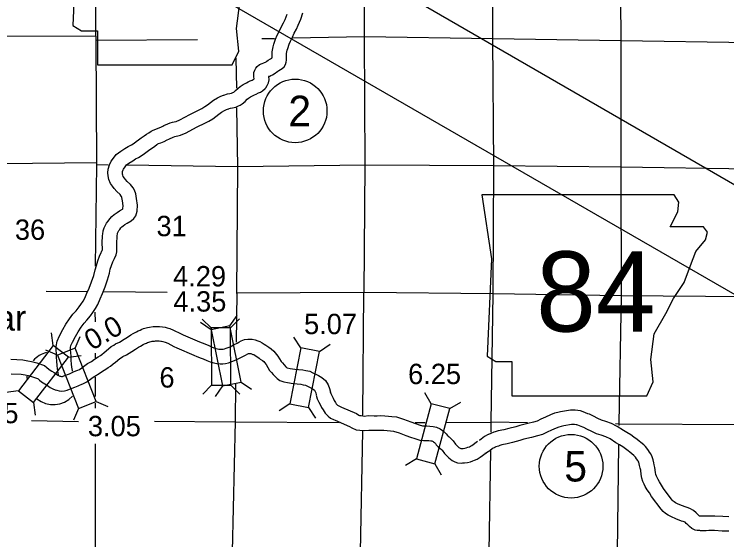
# Model space of a CAD drawing. Extents: x 369523 to 838377, y 495025 to 936819.
# Drawn here: x 509009 to 538589, y 844599 to 866414 of the extents above; entities that cross this region are included whole.
import ezdxf

# ---------------------------------------------------------------- set-up
doc = ezdxf.new("R2010")
doc.units = 0
for name, color, linetype in [('1', 7, 'Continuous'), ('21', 7, 'Continuous'), ('22', 7, 'Continuous'), ('DSN_BRDG_Annotation', 7, 'Continuous'), ('DSN_DRFT_Common-Line', 7, 'Continuous'), ('DSN_DRFT_Junk-No-Plot', 7, 'Continuous'), ('Level 1', 7, 'Continuous'), ('Level 15', 7, 'Continuous'), ('Level 21', 7, 'Continuous'), ('Level 22', 7, 'Continuous')]:
    doc.layers.add(name, color=color, linetype=linetype)

msp = doc.modelspace()

# ---------------------------------------------------------------- linework, layer by layer
at = {"layer": '1'}
for start, end in [(104.6734, 138.959), (176.1329, 180.9903), (231.4918, 316.9545)]:
    msp.add_arc((510629, 851310), 1100, start, end, dxfattribs=at)
at = {"layer": '21'}
for p, q in [((459282, 905322), (715348, 757482)), ((708796, 756692), (471020, 893972))]:
    msp.add_line(p, q, dxfattribs=at)
at = {"layer": '22'}
for points in [[(511222, 872658), (511622, 869994), (511444, 865952), (511799, 865730), (512465, 865730), (512465, 864309), (518061, 864309), (518327, 864887), (518239, 865819), (518372, 866885), (518860, 867729), (519171, 868350), (519615, 869017), (519882, 869727), (520104, 870304), (520503, 870793), (520592, 871104), (520415, 871326), (519038, 871326), (519349, 871948), (519393, 872347), (519209, 872654)], [(528426, 858920), (528825, 856256), (528648, 852215), (529003, 851993), (529669, 851993), (529669, 850571), (535265, 850571), (535531, 851149), (535442, 852081), (535576, 853147), (536064, 853991), (536375, 854613), (536819, 855279), (537086, 855989), (537308, 856567), (537707, 857055), (537796, 857366), (537618, 857588), (536242, 857588), (536553, 858210), (536597, 858610), (536413, 858917)]]:
    msp.add_lwpolyline(points, close=True, dxfattribs=at)
at = {"layer": 'DSN_DRFT_Common-Line'}
for centre in [(520673, 862400), (532128, 847652)]:
    msp.add_circle(centre, 1320, dxfattribs=at)
at = {"layer": 'Level 1'}
for points in [[(517713, 863059), (517859, 863105), (517963, 863119), (518023, 863133), (518061, 863149), (518086, 863163), (518126, 863186), (518201, 863247), (518287, 863332), (518390, 863413), (518512, 863493), (518645, 863566), (518723, 863608), (518800, 863643), (518889, 863684), (518933, 863707), (518952, 863719), (518974, 863739), (518952, 863820), (518952, 863908), (518960, 863991), (518992, 864097), (519042, 864175), (519091, 864239), (519194, 864324), (519298, 864367), (519365, 864390), (519398, 864405), (519442, 864428), (519463, 864440), (519493, 864463), (519553, 864510), (519646, 864567), (519691, 864592), (519714, 864607), (519715, 864616), (519713, 864689), (519712, 864850), (519758, 865061), (519790, 865175), (519862, 865382), (519928, 865545), (520017, 865729), (520103, 865907), (520190, 866064), (520250, 866195), (520341, 866414)], [(517896, 862487), (517992, 862518), (518072, 862529), (518207, 862560), (518317, 862605), (518382, 862640), (518470, 862693), (518601, 862798), (518685, 862882), (518741, 862926), (518822, 862979), (518932, 863039), (518989, 863070), (519048, 863096), (519153, 863145), (519232, 863186), (519316, 863239), (519420, 863333), (519449, 863363), (519512, 863461), (519561, 863571), (519586, 863696), (519572, 863823), (519571, 863827), (519586, 863832), (519661, 863866), (519732, 863903), (519795, 863939), (519856, 863985), (519895, 864015), (519953, 864051), (520000, 864078), (520060, 864116), (520133, 864160), (520213, 864229), (520272, 864324), (520298, 864428), (520306, 864506), (520316, 864589), (520313, 864699), (520312, 864787), (520340, 864916), (520363, 864994), (520424, 865172), (520476, 865302), (520557, 865467), (520636, 865630), (520726, 865794), (520800, 865955), (520906, 866210), (520989, 866479)], [(510845, 851427), (510832, 851533), (510803, 851694), (510794, 851834), (510772, 852015), (510769, 852175), (510757, 852331), (510747, 852464), (510749, 852628), (510785, 852837), (510887, 853059), (511022, 853321), (511153, 853545), (511301, 853766), (511444, 853964), (511574, 854108), (511708, 854263), (511780, 854363), (511868, 854502), (511939, 854628), (512027, 854831), (512117, 855046), (512218, 855304), (512309, 855568), (512375, 855809), (512417, 855990), (512474, 856174), (512550, 856370), (512620, 856524), (512635, 856552), (512664, 856616), (512667, 856631), (512669, 856679), (512662, 856917), (512679, 857231), (512684, 857287), (512706, 857421), (512738, 857543), (512840, 857738), (512902, 857829), (512977, 857928), (513058, 858016), (513161, 858106), (513275, 858185), (513381, 858248), (513509, 858329), (513517, 858335), (513523, 858353), (513529, 858464), (513497, 858669), (513475, 858807), (513458, 858855), (513453, 858864), (513400, 858929), (513262, 859056), (513161, 859176), (513086, 859275), (513011, 859394), (512933, 859555), (512909, 859700), (512900, 859834), (512913, 859982), (512958, 860164), (513033, 860317), (513132, 860437), (513239, 860593), (513434, 860733), (513604, 860837), (513744, 860930), (513873, 860997), (513989, 861064), (514070, 861126), (514169, 861194), (514278, 861280), (514397, 861365), (514501, 861437), (514590, 861498), (514690, 861567), (514777, 861604), (514886, 861640), (514988, 861679), (515092, 861733), (515174, 861774), (515224, 861795), (515382, 861862), (515489, 861904), (515584, 861930), (515649, 861946), (515728, 861968), (515887, 862030), (516295, 862259), (516683, 862445), (516797, 862505), (516919, 862578), (517027, 862659), (517153, 862749), (517285, 862846), (517452, 862948), (517579, 863008), (517698, 863053)], [(511429, 851594), (511425, 851622), (511400, 851766), (511392, 851889), (511371, 852056), (511369, 852204), (511355, 852376), (511347, 852483), (511348, 852574), (511363, 852658), (511426, 852797), (511548, 853032), (511661, 853226), (511794, 853423), (511912, 853587), (512024, 853712), (512179, 853891), (512277, 854027), (512383, 854194), (512477, 854361), (512579, 854596), (512673, 854821), (512781, 855097), (512882, 855390), (512957, 855662), (512997, 855833), (513041, 855977), (513103, 856138), (513155, 856253), (513171, 856281), (513237, 856426), (513265, 856555), (513270, 856676), (513262, 856910), (513278, 857187), (513280, 857212), (513294, 857298), (513301, 857324), (513356, 857430), (513389, 857479), (513437, 857541), (513478, 857586), (513530, 857632), (513599, 857679), (513695, 857737), (513862, 857842), (513971, 857933), (514053, 858049), (514117, 858236), (514132, 858493), (514090, 858764), (514059, 858953), (514006, 859108), (513946, 859208), (513839, 859341), (513696, 859472), (513629, 859552), (513580, 859616), (513537, 859685), (513511, 859739), (513506, 859769), (513502, 859827), (513507, 859883), (513525, 859958), (513540, 859989), (513612, 860075), (513675, 860168), (513766, 860233), (513926, 860331), (514048, 860412), (514162, 860471), (514324, 860565), (514421, 860640), (514525, 860710), (514638, 860800), (514742, 860874), (514841, 860942), (514930, 861003), (514981, 861039), (514990, 861042), (515088, 861075), (515233, 861130), (515363, 861197), (515428, 861229), (515461, 861244), (515610, 861307), (515678, 861334), (515735, 861349), (515801, 861366), (515917, 861397), (516144, 861486), (516571, 861726), (516954, 861909), (517091, 861982), (517255, 862079), (517382, 862175), (517505, 862263), (517620, 862347), (517739, 862419), (517815, 862456), (517911, 862492)], [(511071, 851400), (511300, 851493), (511408, 851537), (511469, 851568), (511567, 851607), (511647, 851636), (511717, 851670), (511809, 851735), (511933, 851839), (512054, 851910), (512210, 852004), (512338, 852097), (512492, 852194), (512589, 852252), (512650, 852292), (512748, 852375), (512831, 852435), (513036, 852616), (513142, 852680), (513219, 852729), (513380, 852807), (513568, 852919), (513714, 853013), (513851, 853100), (513953, 853159), (514084, 853230), (514154, 853266), (514231, 853303), (514301, 853338), (514373, 853365), (514482, 853393), (514537, 853407), (514621, 853430), (514771, 853445), (514843, 853452), (514946, 853453), (515043, 853451), (515170, 853444), (515275, 853422), (515355, 853399), (515468, 853364), (515627, 853304), (515910, 853164), (516020, 853108), (516694, 852813), (516804, 852771), (516984, 852699), (517086, 852661), (517229, 852597), (517340, 852557), (517452, 852520), (517502, 852509), (517567, 852505), (517628, 852505), (517683, 852512), (517742, 852524), (517807, 852549), (517892, 852579), (517968, 852612), (518046, 852652), (518113, 852689), (518267, 852765), (518337, 852797), (518434, 852850), (518575, 852917), (518707, 852930), (518804, 852931), (518884, 852931), (519013, 852898), (519117, 852861), (519201, 852832), (519305, 852771), (519384, 852722), (519456, 852672), (519532, 852620), (519573, 852587), (519679, 852518), (519786, 852422), (519848, 852355), (519955, 852225), (520090, 851997), (520141, 851943), (520214, 851857), (520289, 851773), (520310, 851753), (520346, 851742), (520471, 851715), (520663, 851680), (520808, 851671), (520994, 851646), (521117, 851625), (521285, 851592), (521410, 851533), (521532, 851476), (521647, 851414), (521774, 851338), (521930, 851205), (522036, 851037), (522102, 850879), (522132, 850728)], [(511298, 850844), (511527, 850938), (511658, 850991), (511716, 851021), (511781, 851047), (511880, 851083), (512021, 851151), (512175, 851259), (512281, 851348), (512360, 851394), (512541, 851503), (512675, 851600), (512808, 851684), (512906, 851743), (513007, 851808), (513119, 851903), (513207, 851967), (513391, 852129), (513460, 852170), (513514, 852205), (513664, 852278), (513885, 852409), (514037, 852508), (514162, 852587), (514247, 852636), (514363, 852699), (514420, 852728), (514494, 852764), (514539, 852786), (514554, 852792), (514633, 852812), (514689, 852827), (514729, 852837), (514834, 852848), (514878, 852853), (514942, 852853), (515021, 852852), (515089, 852848), (515128, 852840), (515184, 852824), (515274, 852796), (515388, 852753), (515640, 852628), (515763, 852566), (516467, 852257), (516586, 852212), (516769, 852139), (516859, 852106), (517004, 852040), (517144, 851989), (517293, 851940), (517422, 851912), (517552, 851905), (517667, 851906), (517779, 851920), (517908, 851945), (518014, 851985), (518112, 852020), (518223, 852069), (518328, 852122), (518392, 852157), (518525, 852223), (518606, 852260), (518707, 852316), (518737, 852330), (518737, 852330), (518808, 852331), (518811, 852331), (518837, 852324), (518918, 852295), (518950, 852284), (518994, 852258), (519055, 852220), (519115, 852179), (519172, 852140), (519219, 852101), (519313, 852040), (519366, 851993), (519396, 851960), (519462, 851879), (519609, 851632), (519694, 851543), (519762, 851463), (519855, 851359), (519920, 851294), (520036, 851209), (520195, 851161), (520353, 851126), (520592, 851083), (520750, 851074), (520904, 851053), (521008, 851035), (521096, 851018), (521155, 850990), (521261, 850940), (521350, 850892), (521423, 850849), (521472, 850807), (521502, 850760), (521525, 850703), (521544, 850609)], [(508870, 852095), (509368, 852067), (509571, 852033), (509732, 851998), (509949, 851937), (510260, 851831), (510368, 851747), (510450, 851684), (510500, 851637), (510568, 851596), (510665, 851547), (510762, 851472), (510817, 851429), (510850, 851413), (510897, 851395), (510927, 851386), (510970, 851376), (510982, 851375), (511016, 851376), (511066, 851398)], [(508886, 851493), (509301, 851470), (509457, 851443), (509587, 851416), (509770, 851363), (509970, 851296), (509999, 851273), (510062, 851225), (510136, 851156), (510276, 851071), (510343, 851037), (510394, 850997), (510503, 850913), (510613, 850862), (510707, 850825), (510777, 850806), (510877, 850781), (510970, 850774), (511094, 850778), (511203, 850803), (511303, 850846)], [(522130, 850739), (522147, 850666), (522191, 850584), (522247, 850474), (522291, 850382), (522342, 850302), (522380, 850237), (522390, 850222), (522403, 850208), (522423, 850190), (522450, 850168), (522507, 850146), (522595, 850100), (523215, 849837), (523314, 849770), (523347, 849756), (523412, 849751), (523554, 849735), (523699, 849755), (523951, 849750), (524074, 849750), (524199, 849753), (524394, 849750), (524551, 849730), (524689, 849719), (524879, 849696), (525174, 849605), (525476, 849495), (525662, 849428), (525823, 849372), (525963, 849330), (526029, 849324), (526076, 849323), (526140, 849323), (526258, 849317), (526407, 849305), (526544, 849269), (526689, 849205), (526785, 849139), (526853, 849079), (526938, 849003), (526992, 848928), (527021, 848898), (527061, 848866), (527151, 848788), (527236, 848707), (527333, 848563), (527400, 848498), (527442, 848453), (527473, 848431), (527517, 848397), (527543, 848384), (527550, 848384), (527586, 848385), (527645, 848389), (527715, 848400), (527770, 848413), (527840, 848438), (527907, 848462), (527953, 848480), (528012, 848518), (528244, 848690)], [(521547, 850598), (521582, 850452), (521659, 850307), (521708, 850209), (521765, 850090), (521831, 849987), (521869, 849924), (521911, 849856), (521983, 849778), (522035, 849732), (522144, 849643), (522259, 849598), (522339, 849557), (522927, 849307), (523028, 849240), (523202, 849167), (523354, 849154), (523562, 849131), (523733, 849154), (523947, 849150), (524083, 849151), (524201, 849153), (524350, 849151), (524488, 849133), (524629, 849121), (524754, 849106), (524983, 849036), (525272, 848930), (525462, 848863), (525637, 848801), (525849, 848737), (525994, 848725), (526070, 848723), (526126, 848723), (526219, 848718), (526305, 848711), (526344, 848701), (526396, 848678), (526416, 848665), (526455, 848630), (526491, 848598), (526529, 848545), (526613, 848456), (526677, 848405), (526747, 848344), (526775, 848318), (526871, 848175), (526973, 848077), (527046, 847998), (527116, 847949), (527196, 847888), (527296, 847837), (527415, 847786), (527558, 847783), (527618, 847786), (527707, 847792), (527831, 847810), (527945, 847838), (528042, 847873), (528114, 847899), (528227, 847942), (528354, 848025), (528602, 848208)], [(538669, 845555), (538421, 845562), (538094, 845577), (537937, 845580), (537829, 845581), (537716, 845574), (537612, 845573), (537554, 845574), (537461, 845581), (537437, 845601), (537397, 845639), (537320, 845718), (537203, 845819), (537063, 845897), (536952, 845933), (536906, 845947), (536714, 846021), (536551, 846094), (536466, 846136), (536403, 846178), (536367, 846207), (536330, 846249), (535964, 846729), (535884, 846868), (535793, 846998), (535736, 847094), (535710, 847152), (535673, 847237), (535650, 847306), (535636, 847397), (535606, 847601), (535577, 847711), (535560, 847795), (535538, 847913), (535491, 848047), (535439, 848161), (535386, 848235), (535337, 848308), (535272, 848398), (535213, 848465), (535149, 848537), (535028, 848631), (534952, 848695), (534873, 848764), (534737, 848860), (534608, 848951), (534443, 849058), (534299, 849134), (534045, 849305), (533802, 849420), (533572, 849508), (533391, 849561), (533244, 849630), (533053, 849725), (532888, 849808), (532821, 849832), (532625, 849911), (532514, 849951), (532405, 849970), (532298, 849977), (532109, 849982), (531693, 849913), (531579, 849881), (531432, 849852), (531269, 849781), (531068, 849691), (530874, 849605), (530717, 849528), (530569, 849485), (530337, 849421), (530004, 849348), (529826, 849289), (529537, 849214), (529341, 849161), (529102, 849118), (528980, 849078), (528926, 849059), (528791, 849014), (528704, 848975)], [(538669, 844954), (538398, 844962), (538075, 844977), (537928, 844980), (537844, 844981), (537738, 844974), (537611, 844973), (537493, 844975), (537473, 844978), (537361, 844987), (537276, 845004), (537138, 845071), (537038, 845151), (536973, 845215), (536909, 845280), (536857, 845325), (536821, 845345), (536776, 845359), (536714, 845377), (536482, 845467), (536296, 845551), (536164, 845615), (536047, 845695), (535954, 845769), (535867, 845866), (535462, 846396), (535376, 846547), (535289, 846672), (535204, 846815), (535161, 846909), (535112, 847023), (535066, 847162), (535043, 847306), (535017, 847481), (534992, 847576), (534972, 847679), (534957, 847757), (534934, 847823), (534917, 847860), (534893, 847893), (534845, 847964), (534801, 848025), (534763, 848069), (534738, 848096), (534651, 848164), (534562, 848239), (534501, 848292), (534392, 848370), (534272, 848453), (534139, 848540), (533991, 848618), (533748, 848782), (533566, 848868), (533380, 848939), (533177, 848999), (532983, 849090), (532785, 849188), (532654, 849255), (532609, 849270), (532409, 849351), (532359, 849369), (532336, 849373), (532271, 849377), (532149, 849381), (531824, 849327), (531719, 849297), (531612, 849276), (531512, 849232), (531312, 849143), (531128, 849061), (530935, 848967), (530733, 848907), (530480, 848838), (530163, 848769), (529996, 848713), (529691, 848634), (529473, 848576), (529250, 848535), (529172, 848509), (529119, 848491), (529008, 848454), (528948, 848427)], [(528689, 848968), (528536, 848889), (528399, 848781), (528333, 848737), (528307, 848726)], [(528963, 848434), (528862, 848382), (528753, 848296), (528620, 848206), (528539, 848173)]]:
    msp.add_lwpolyline(points, dxfattribs=at)
at = {"layer": 'Level 15'}
for points in [[(512401, 865502), (512381, 870748), (512380, 870824), (512358, 876028)], [(512401, 865502), (512400, 865320), (512419, 860240), (512421, 860162), (512372, 855951)], [(512056, 854894), (510337, 854909)], [(515352, 854864), (512732, 854888)], [(528893, 854803), (523543, 854865), (523503, 854861), (518255, 854837), (518221, 854838)], [(549623, 854534), (544781, 854632), (539490, 854682), (539446, 854681), (534205, 854724), (528893, 854803)], [(512361, 854052), (512362, 853649)], [(512364, 852338), (512364, 852150)], [(512365, 851355), (512367, 850544)], [(512367, 850276), (512368, 850061)], [(512368, 848578), (512365, 844229), (512361, 844207), (512365, 838913), (512342, 833591)]]:
    msp.add_lwpolyline(points, dxfattribs=at)
at = {"layer": 'Level 21'}
for p, q in [((517191, 853391), (516815, 853762)), ((517964, 853473), (518258, 853912)), ((517982, 853396), (518354, 853771)), ((517187, 853319), (516748, 853613)), ((510630, 852666), (510562, 853189)), ((511535, 852550), (511743, 853035)), ((520905, 852572), (520611, 853011)), ((521682, 852419), (522121, 852713)), ((510799, 852257), (510314, 852466)), ((511257, 852182), (511781, 852250)), ((518426, 851143), (518865, 850849)), ((509180, 850784), (508656, 850716)), ((517205, 851015), (516834, 850639)), ((517650, 850989), (517356, 850550)), ((517997, 851020), (518373, 850648)), ((526322, 850247), (526057, 850704)), ((509807, 850300), (509875, 849777)), ((512414, 850343), (512899, 850134)), ((520445, 850241), (520006, 849947)), ((527087, 850043), (527544, 850307)), ((511678, 850050), (511470, 849565)), ((521222, 850088), (521516, 849649)), ((525709, 847952), (525252, 847687)), ((526474, 847747), (526738, 847290))]:
    msp.add_line(p, q, dxfattribs=at)
for points in [[(517187, 853319), (517650, 850989), (518426, 851143), (517964, 853473)], [(517997, 851020), (517982, 853396), (517191, 853391), (517205, 851015)], [(509807, 850300), (511257, 852182), (510630, 852666), (509180, 850784)], [(510799, 852257), (511678, 850050), (512414, 850343), (511535, 852550)], [(521222, 850088), (521682, 852419), (520905, 852572), (520445, 850241)], [(526474, 847747), (527087, 850043), (526322, 850247), (525709, 847952)]]:
    msp.add_lwpolyline(points, close=True, dxfattribs=at)
at = {"layer": 'Level 22'}
for points in [[(528893, 854803), (528920, 860117), (528875, 865382), (528864, 870662)], [(534149, 870592), (534196, 865312), (534193, 860059), (534205, 854724)], [(523556, 865480), (523530, 868345)], [(512401, 865502), (507094, 865490), (501808, 865446), (496509, 865481), (491193, 865415), (491205, 860171), (491149, 854952)], [(516611, 865353), (512400, 865320)], [(519819, 865400), (519288, 865388)], [(528873, 865388), (523556, 865480), (520567, 865416)], [(523543, 854865), (523574, 860164), (523556, 865480)], [(544790, 865240), (539569, 865231), (534196, 865312), (528873, 865388)], [(518244, 863341), (518228, 864593)], [(518255, 854837), (518286, 860084), (518255, 862522)], [(512419, 860240), (507093, 860186), (501858, 860132), (496496, 860149), (491203, 860195)], [(512912, 860155), (512421, 860162)], [(528908, 860115), (523588, 860146), (518272, 860074), (513687, 860143)], [(547802, 859935), (544841, 859976), (539572, 859984), (534193, 860059), (528908, 860115)], [(518255, 854837), (518226, 852796)], [(523503, 854861), (523474, 849776)], [(528807, 849070), (528813, 849477), (528893, 854803)], [(534205, 854724), (534106, 849436), (534105, 849349)], [(518201, 851055), (518179, 849513), (518057, 844114), (517984, 838785), (517903, 835206)], [(509729, 849554), (511673, 849514)], [(514832, 849523), (518168, 849495), (522496, 849465)], [(525660, 849466), (526071, 849468)], [(526940, 849471), (528813, 849477)], [(530314, 849456), (528813, 849477)], [(544743, 849334), (539364, 849375), (534117, 849404), (533969, 849406)], [(523465, 849111), (523365, 844096), (523330, 839220)], [(534094, 848535), (534033, 844070), (533928, 838759), (533825, 834274)], [(528663, 839240), (528732, 844101), (528795, 848299)]]:
    msp.add_lwpolyline(points, dxfattribs=at)

# ---------------------------------------------------------------- texts
at = {"layer": '1'}
msp.add_text('Cedar', height=1056, dxfattribs=at).set_placement((505666, 853278))
at = {"layer": '22'}
msp.add_text('84', height=3326.4, dxfattribs=at).set_placement((530677, 853243))
at = {"layer": 'DSN_BRDG_Annotation'}
msp.add_text('0.0', height=844.8, rotation=30, dxfattribs=at).set_placement((512233, 852435))
at = {"layer": 'DSN_DRFT_Common-Line'}
for s, p in [('2', (520390, 861766)), ('5', (531845, 847018))]:
    msp.add_text(s, height=1267, dxfattribs=at).set_placement(p)
at = {"layer": 'DSN_DRFT_Junk-No-Plot'}
for s, p in [('4.29', (515604, 855117)), ('4.35', (515616, 854071)), ('5.07', (521040, 853134)), ('6.25', (525360, 851061)), ('2.75', (506985, 849436)), ('3.05', (512066, 848896))]:
    msp.add_text(s, height=844.8, dxfattribs=at).set_placement(p)
at = {"layer": 'Level 22'}
for s, height, p in [('36', 844.8, (509036, 857049)), ('31', 844.8, (514913, 857201)), ('6', 845, (515036, 850916))]:
    msp.add_text(s, height=height, dxfattribs=at).set_placement(p)

doc.saveas('drawing.dxf')
